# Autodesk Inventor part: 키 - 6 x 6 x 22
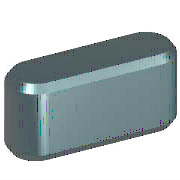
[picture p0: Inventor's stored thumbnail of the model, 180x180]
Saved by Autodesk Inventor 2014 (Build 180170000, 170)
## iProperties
IsCustomPart: 1
Created: 2012-02
Part Number: 키 - 6 x 6 x 22
Material: 강철, 연강
Description: 키 및 해당 키홈
Document SubType Name: Modeling
Standard: KS B 1311
Designer: mduedu
Standards Organization: KS
Language: ko-KR
Size Designation: 6 x 6 x 22
Categories: <MemberInstance><Categories><Category DisplayName="샤프트 부품" InternalName="7f7aeb1f-a693-4053-b835-cee3144e0d98" Mnemonic="SHFT"><Category DisplayName="키" Interna
Density: 7.86 g/cm^3
Mass: 5.79788 g
Surface Area: 5.294 cm^2
Volume: 0.737644 cm^3
Appearance: 강철
Author: mduedu
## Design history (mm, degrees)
workplane "Work Plane1"
workplane "Work Plane2"
sketch "스케치1"
  geometry: L1 (3, 3)-(19, 3); L2 (19, -3)-(3, -3); L3 (0, 9.4)-(0, -7.4) reference; L4 (-5, 0)-(30, 0) reference; L5 (22, 0)-(22, 7); A1 r 3 centre (3, 0) between (3, 3) and (3, -3); A2 r 3 centre (19, 0) between (19, -3) and (19, 3)
  constraints: 6 end point, 5 point on circle, 4 tangent, 3 point on line, 2 centre point, 1 horizontal, 1 parallel, 1 perpendicular
  dimensions: "d0" = 3 radius of A1 (= 0.5 x PB); "d13" = 3 radius of A2 (= 0.5 x PB); "d14" = 22 distance between parallel lines of L5 L3 (= NLG)
extrude "본체1" new body sketch "스케치1" taper "d3" = 0 deg; stored distance "d4" = 10
workplane "Work Plane3"
body "Solid1"
chamfer "모따기1" distance "d8" = 0.4 (= PHH); stored, may be unused: second distance "d9" = 0.4 (= PHH), angle "d15" = 45 deg
other parameters: "d1" = -3.5 (= -PNT), "d2" = 2.5 (= PH - PNT), "NLG" = 22 [user parameter; used in 3 equation terms], "PB" = 6 [user parameter; used in 2 equation terms], "PNT" = 3.5 [user parameter; used in 2 equation terms], "PH" = 6 [user parameter; used in 1 equation term], "PHH" = 0.4 [user parameter; used in 2 equation terms], "d10" = 0, "d16" = 0, "d17" = 0, "d18" = 0, "WDMIN" = 17 [user parameter], "PLB2" = 22 (= NLG) [user parameter], "WDMAX" = 22 [user parameter], "PLB1" = 22 (= NLG) [user parameter], "RR" = 0.16 [user parameter], "PUEB" = 2.8 [user parameter]
